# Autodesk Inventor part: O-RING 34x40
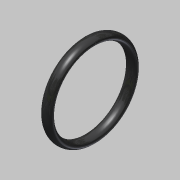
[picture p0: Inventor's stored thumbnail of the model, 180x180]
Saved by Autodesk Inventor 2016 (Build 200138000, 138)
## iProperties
Created: 2020-02
Part Number: O-RING 34x40
Material: 고무
Document SubType Name: Modeling
Designer: mduedu
Density: 1 g/cm^3
Appearance: 고무 - 검은색 - 버전 1.1
Author: mduedu
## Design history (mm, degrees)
sketch "스케치1"
  geometry: L1 (-3.29, 0)-(3.29, 0) reference; L2 (-2.35, 18.5)-(2.35, 18.5); L3 (0, 20)-(0, 17); 6 further points; 1 other entity
  constraints: 4 coincident, 4 end point, 2 horizontal, 2 midpoint, 1 vertical, 1 vertical alignment, 6 other
  dimensions: "d0" = 34 diameter of point (0, 17) L1; "d1" = 40 diameter of point (0, 20) L1; "d2" = 2.35 distance from line of point (2.35, 18.5) L3
revolve "회전1" sketch "스케치1" stored, may be unused: angle "d3" = 90 deg
node "솔리드1"
